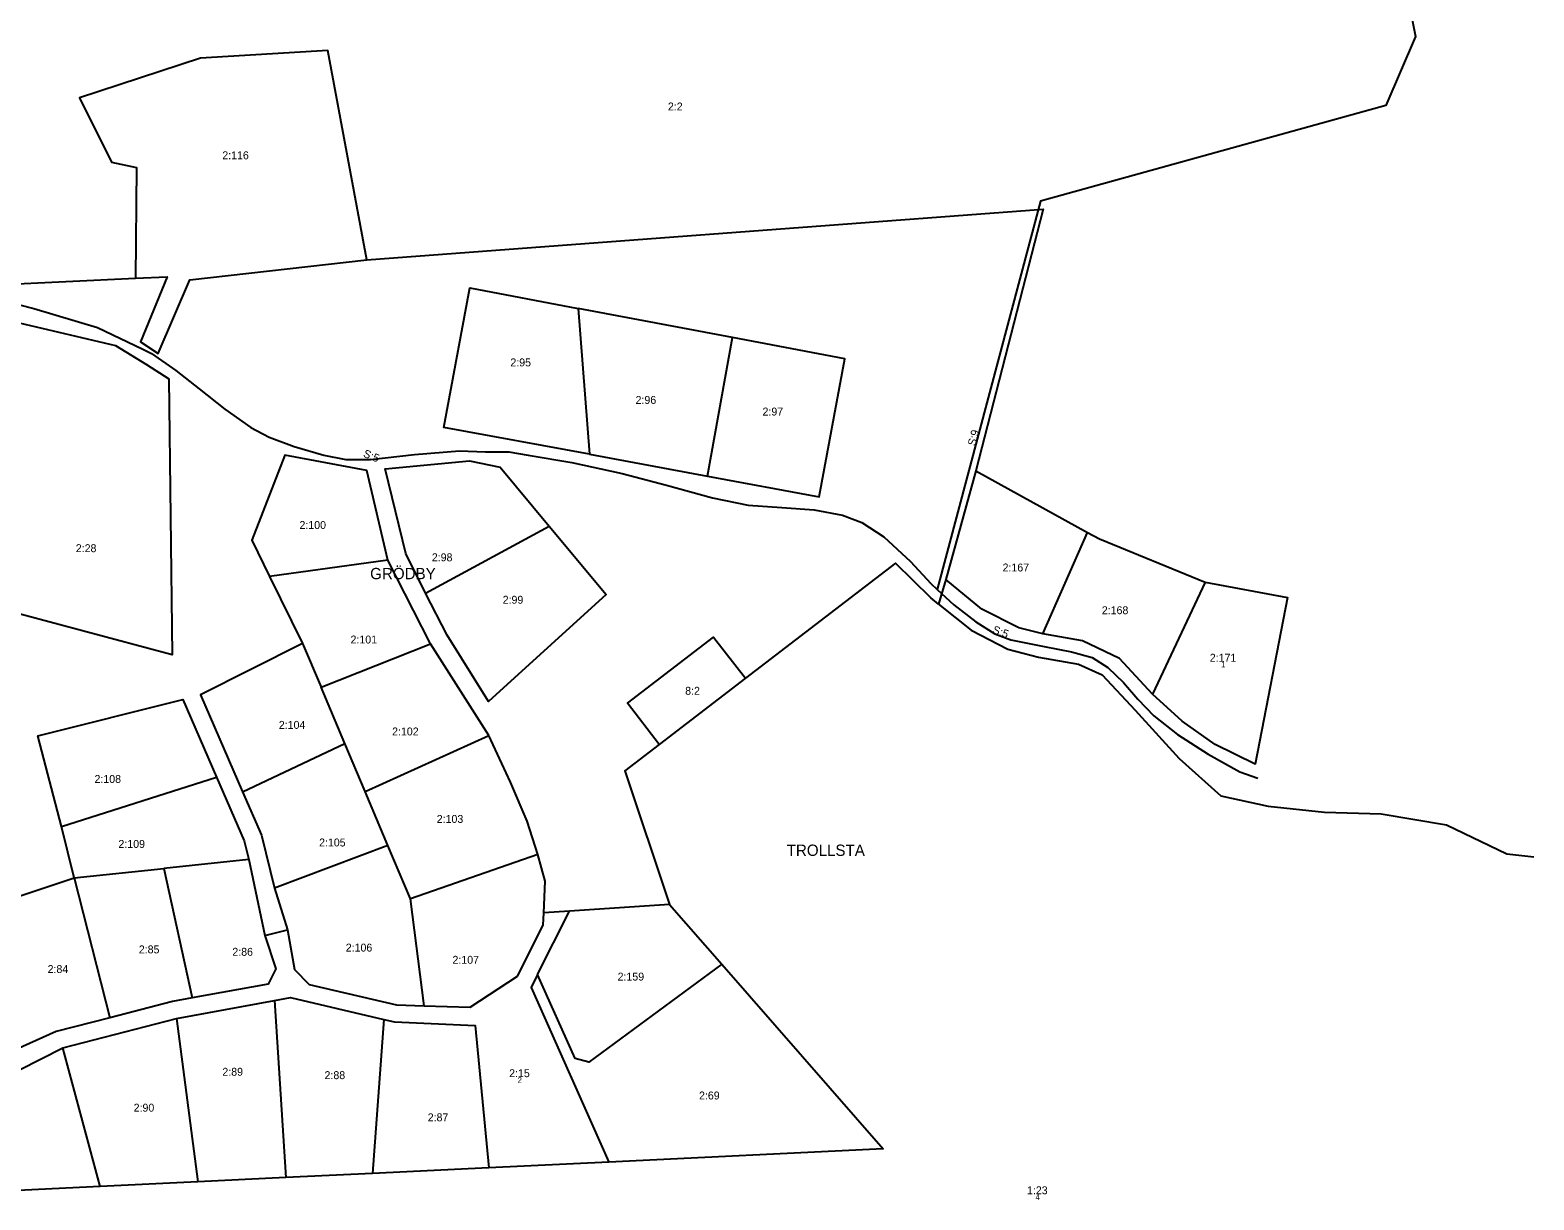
# Model space of a CAD drawing. Extents: x 140824 to 143748, y 6547319 to 6550906.
# Drawn here: x 142666 to 143330, y 6548234 to 6548751 of the extents above; entities that cross this region are included whole.
import ezdxf

# ---------------------------------------------------------------- set-up
doc = ezdxf.new("R2010")
doc.units = 0
for name, color, linetype in [('FAST Fastighetsgräns', 7, 'Continuous'), ('FAST Mittlinjeredovisad samfällighet', 7, 'Continuous'), ('FAST Områdesnummer för fastighet', 7, 'Continuous'), ('FAST Registernummer för fastighet', 7, 'Continuous'), ('FAST Registernummer för mittlinjeredovisad samfällighet', 7, 'Continuous'), ('FAST Traktgräns', 7, 'Continuous'), ('FAST Traktnamn', 7, 'Continuous')]:
    doc.layers.add(name, color=color, linetype=linetype)

msp = doc.modelspace()

# ---------------------------------------------------------------- linework, layer by layer
at = {"layer": 'FAST Fastighetsgräns'}
for p, q in [((142618.17, 6548636.75), (142712.61, 6548641.27)), ((142908.09, 6548627.94), (142913.14, 6548563.46)), ((142976.36, 6548615.05), (142908.09, 6548627.94)), ((142965.31, 6548553.78), (142976.36, 6548615.05)), ((142913.14, 6548563.46), (142965.31, 6548553.78)), ((143083.86, 6548556.1), (143070.63, 6548508.13)), ((143083.86, 6548556.1), (143133.14, 6548528.94)), ((142840.68, 6548502.06), (142895.37, 6548531.69)), ((143113.37, 6548484.13), (143133.14, 6548528.94)), ((142824.13, 6548516.71), (142771.89, 6548509.52)), ((142843, 6548479.64), (142824.13, 6548516.71)), ((142771.89, 6548509.52), (142786.42, 6548479.81)), ((143070.63, 6548508.13), (143067.39, 6548497.31)), ((143185.15, 6548507), (143161.85, 6548457.49)), ((142786.42, 6548479.81), (142794.6, 6548460.52)), ((142794.6, 6548460.52), (142843, 6548479.64)), ((142868.63, 6548439.14), (142843, 6548479.64)), ((142805.09, 6548435.69), (142794.6, 6548460.52)), ((142814.05, 6548414.47), (142868.63, 6548439.14)), ((142759.95, 6548414.34), (142805.09, 6548435.69)), ((142814.05, 6548414.47), (142805.09, 6548435.69)), ((142679.88, 6548398.95), (142748.42, 6548420.75)), ((142824.15, 6548390.52), (142814.05, 6548414.47)), ((142685.57, 6548376.24), (142679.88, 6548398.95)), ((142824.15, 6548390.52), (142774.09, 6548371.73)), ((142834.03, 6548367.09), (142824.15, 6548390.52)), ((142890.33, 6548386.56), (142834.03, 6548367.09)), ((142685.57, 6548376.24), (142725.17, 6548380.4)), ((142762.71, 6548384.37), (142725.17, 6548380.4)), ((142725.17, 6548380.4), (142737.73, 6548323.24)), ((142762.71, 6548384.37), (142769.73, 6548350.79)), ((142645.15, 6548362.91), (142685.57, 6548376.24)), ((142685.57, 6548376.24), (142701.23, 6548314.47)), ((142774.09, 6548371.73), (142779.84, 6548353.38)), ((142840.21, 6548319.76), (142834.03, 6548367.09)), ((142890.27, 6548333.56), (142904.29, 6548361.63)), ((142892.68, 6548355.38), (142892.95, 6548360.89)), ((142904.29, 6548361.63), (142892.95, 6548360.89)), ((142948.48, 6548364.53), (142904.29, 6548361.63)), ((142769.73, 6548350.79), (142779.84, 6548353.38)), ((142730.78, 6548314.13), (142774.07, 6548322.1)), ((142774.07, 6548322.1), (142779, 6548243.85)), ((142680.48, 6548301.15), (142730.78, 6548314.13)), ((142730.78, 6548314.13), (142740.17, 6548241.99)), ((142822.37, 6548313.69), (142817.31, 6548245.69)), ((142697.01, 6548239.92), (142680.48, 6548301.15))]:
    msp.add_line(p, q, dxfattribs=at)
for points in [[(142814.85, 6548649.35), (142797.52, 6548741.86), (142741.41, 6548738.46), (142687.9, 6548720.98), (142702.08, 6548692.57), (142713.02, 6548690.26), (142712.61, 6548641.27)], [(142814.85, 6548649.35), (143113.56, 6548671.83), (143083.86, 6548556.1)], [(142712.61, 6548641.27), (142726.63, 6548641.87), (142714.8, 6548613.21), (142722.65, 6548607.98), (142736.59, 6548640.58), (142814.85, 6548649.35)], [(142913.14, 6548563.46), (142848.87, 6548575.34), (142860.28, 6548636.97), (142908.09, 6548627.94)], [(142646.14, 6548625.16), (142703.75, 6548611.52), (142717.51, 6548603.13), (142727.33, 6548596.85), (142728.81, 6548474.79), (142649.42, 6548496.06), (142646.9, 6548582.14)], [(142965.31, 6548553.78), (143014.57, 6548544.64), (143025.98, 6548605.68), (142976.36, 6548615.05)], [(142824.13, 6548516.71), (142814.79, 6548556.34), (142778.63, 6548563.07), (142764.05, 6548525.53), (142771.89, 6548509.52)], [(142840.68, 6548502.06), (142832.03, 6548519.62), (142822.9, 6548557.08), (142860.16, 6548560.53), (142873.64, 6548557.73), (142895.37, 6548531.69)], [(142895.37, 6548531.69), (142920.6, 6548501.5), (142868.61, 6548454.18), (142850.32, 6548483.52), (142840.68, 6548502.06)], [(143133.14, 6548528.94), (143138.4, 6548526.05), (143185.15, 6548507)], [(143113.37, 6548484.13), (143102.76, 6548486.73), (143086.54, 6548495.05), (143070.63, 6548508.13)], [(143185.15, 6548507), (143221.51, 6548500.22), (143207.27, 6548426.5), (143189.47, 6548435.21), (143174.99, 6548445.57), (143161.85, 6548457.49)], [(142786.42, 6548479.81), (142741.27, 6548457.12), (142759.95, 6548414.34)], [(142944, 6548435.22), (142929.93, 6548453.42), (142967.94, 6548482.71), (142982.06, 6548464.49)], [(143161.85, 6548457.49), (143147.24, 6548473.19), (143130.95, 6548480.99), (143113.37, 6548484.13)], [(142679.88, 6548398.95), (142669.51, 6548438.98), (142733.58, 6548455.15), (142748.42, 6548420.75)], [(142890.33, 6548386.56), (142885.7, 6548401.3), (142878.2, 6548418.51), (142868.63, 6548439.14)], [(142748.42, 6548420.75), (142760.67, 6548392.59), (142762.71, 6548384.37)], [(142759.95, 6548414.34), (142768.31, 6548395.09), (142774.09, 6548371.73)], [(142892.95, 6548360.89), (142893.65, 6548374.8), (142890.33, 6548386.56)], [(142779.84, 6548353.38), (142782.93, 6548335.8), (142789.27, 6548329.22), (142827.93, 6548320.14), (142840.21, 6548319.76)], [(142840.21, 6548319.76), (142860.43, 6548319.12), (142881.42, 6548332.85), (142892.68, 6548355.38)], [(142769.73, 6548350.79), (142774.64, 6548336.15), (142771.29, 6548329.36), (142737.73, 6548323.24)], [(142890.27, 6548333.56), (142887.37, 6548327.77), (142921.74, 6548250.71)], [(142971.6, 6548338.08), (142912.91, 6548294.83), (142906.83, 6548296.4), (142890.27, 6548333.56)], [(142737.73, 6548323.24), (142728.99, 6548321.63), (142701.23, 6548314.47)], [(142774.07, 6548322.1), (142781.07, 6548323.4), (142822.37, 6548313.69)], [(142701.23, 6548314.47), (142677.59, 6548308.34), (142659.85, 6548300.41)], [(142822.37, 6548313.69), (142827.02, 6548312.6), (142862.72, 6548310.98), (142868.65, 6548248.16)], [(142651.5, 6548237.73), (142632.54, 6548276.83), (142680.48, 6548301.15)]]:
    msp.add_lwpolyline(points, dxfattribs=at)
at = {"layer": 'FAST Mittlinjeredovisad samfällighet'}
for points in [[(143234.89, 6549393.41), (143243.33, 6549370.27), (143239.71, 6549334.33), (143247.94, 6549202.7), (143248.16, 6549146.76), (143245.57, 6549060.28), (143250.92, 6548948.02), (143274.15, 6548856.65), (143269.58, 6548790.05), (143278.08, 6548748.05), (143264.92, 6548717.61), (143112.43, 6548675.34), (143066.69, 6548503.76)], [(142644, 6548633.91), (142667.73, 6548627.94), (142695.79, 6548619.5), (142715.82, 6548609.93), (142719.66, 6548607.96), (142730.44, 6548600.46), (142740.77, 6548592.39), (142752.09, 6548583.4), (142763.59, 6548575.3), (142771.68, 6548571.1), (142782.71, 6548566.97), (142795.8, 6548563.07), (142805.57, 6548561.17), (142816.42, 6548561.15), (142835.84, 6548563.38), (142855.69, 6548565), (142867.26, 6548564.52), (142877.53, 6548564.52), (142886.14, 6548563.09), (142905.41, 6548559.89), (142927.57, 6548555), (142947.22, 6548549.88), (142967.44, 6548544.16), (142983.19, 6548540.92), (142998.12, 6548539.9), (143012.46, 6548538.9), (143024.86, 6548536.64), (143033.42, 6548533.31), (143043.21, 6548527.01), (143054.93, 6548516.11), (143063.88, 6548506.32), (143066.69, 6548503.76), (143074.17, 6548496.93), (143083.78, 6548489.46), (143092.28, 6548484.08), (143099.25, 6548481.54), (143113.97, 6548478.47), (143126.08, 6548476.21), (143135.25, 6548473.6), (143142.16, 6548469.29), (143149.01, 6548462.64), (143155.4, 6548455.27), (143162.37, 6548447.88), (143172.84, 6548439.66), (143186.37, 6548430.91), (143200.38, 6548423.17), (143208.39, 6548420.28)]]:
    msp.add_lwpolyline(points, dxfattribs=at)
at = {"layer": 'FAST Traktgräns'}
for p, q in [((142982.06, 6548464.49), (142944, 6548435.22)), ((142948.48, 6548364.53), (142971.6, 6548338.08)), ((142868.65, 6548248.16), (142817.31, 6548245.69)), ((142921.74, 6548250.71), (142868.65, 6548248.16)), ((142697.01, 6548239.92), (142651.5, 6548237.73)), ((142740.17, 6548241.99), (142697.01, 6548239.92)), ((142779, 6548243.85), (142740.17, 6548241.99)), ((142817.31, 6548245.69), (142779, 6548243.85))]:
    msp.add_line(p, q, dxfattribs=at)
for points in [[(143067.39, 6548497.31), (143063.96, 6548500.01), (143048.3, 6548515.42), (142982.06, 6548464.49)], [(143067.39, 6548497.31), (143081.73, 6548485.71), (143097.97, 6548477.39), (143111.53, 6548473.79), (143129.1, 6548470.65), (143139.55, 6548466.04), (143154.16, 6548450.34), (143173.56, 6548429.09), (143192.09, 6548412.56), (143212.96, 6548407.96), (143237.88, 6548405.25), (143262.87, 6548404.54), (143291.73, 6548399.71), (143318.37, 6548386.95), (143330.33, 6548385.61)], [(142944, 6548435.22), (142928.79, 6548423.52), (142948.48, 6548364.53)], [(142971.6, 6548338.08), (143042.86, 6548256.53), (142921.74, 6548250.71)]]:
    msp.add_lwpolyline(points, dxfattribs=at)

# ---------------------------------------------------------------- texts
at = {"layer": 'FAST Områdesnummer för fastighet'}
for s, p in [('1', (143192.18, 6548469.31)), ('2', (142881.46, 6548285.71)), ('4', (143110.18, 6548233.95))]:
    msp.add_text(s, height=2.5, dxfattribs=at).set_placement(p)
at = {"layer": 'FAST Registernummer för fastighet'}
for s, p in [('2:2', (142947.8, 6548715.42)), ('2:116', (142750.97, 6548693.86)), ('2:95', (142878.22, 6548602.33)), ('2:96', (142933.52, 6548585.74)), ('2:97', (142989.6, 6548580.61)), ('2:100', (142785.06, 6548530.46)), ('2:28', (142686.26, 6548520.22)), ('2:98', (142843.53, 6548516.18)), ('2:167', (143095.64, 6548511.69)), ('2:99', (142874.82, 6548497.43)), ('2:168', (143139.47, 6548492.8)), ('2:101', (142807.62, 6548479.86)), ('2:171', (143187.16, 6548471.81)), ('8:2', (142955.42, 6548457.2)), ('2:104', (142775.95, 6548442.14)), ('2:102', (142825.97, 6548439.23)), ('2:108', (142694.52, 6548418.24)), ('2:103', (142845.69, 6548400.57)), ('2:109', (142705.1, 6548389.53)), ('2:105', (142793.72, 6548390.17)), ('2:85', (142714.09, 6548342.91)), ('2:106', (142805.5, 6548343.7)), ('2:86', (142755.4, 6548341.85)), ('2:107', (142852.65, 6548338.32)), ('2:84', (142673.81, 6548334.23)), ('2:159', (142925.58, 6548330.9)), ('2:89', (142751, 6548288.83)), ('2:88', (142796.14, 6548287.34)), ('2:15', (142877.68, 6548288.21)), ('2:69', (142961.55, 6548278.36)), ('2:90', (142711.81, 6548272.96)), ('2:87', (142841.71, 6548268.7)), ('1:23', (143106.42, 6548236.45))]:
    msp.add_text(s, height=3.5, dxfattribs=at).set_placement(p)
at = {"layer": 'FAST Registernummer för mittlinjeredovisad samfällighet'}
for s, rotation, p in [('S:9', 75.24, (143083.55, 6548566.96)), ('S:5', 337.65465, (142812.92, 6548562.51)), ('S:5', 340.129, (143090.92, 6548484.57))]:
    msp.add_text(s, height=3.5, rotation=rotation, dxfattribs=at).set_placement(p)
at = {"layer": 'FAST Traktnamn'}
for s, p in [('GRÖDBY', (142816.28, 6548508.26)), ('TROLLSTA', (143000.25, 6548385.99))]:
    msp.add_text(s, height=5, dxfattribs=at).set_placement(p)

doc.saveas('drawing.dxf')
